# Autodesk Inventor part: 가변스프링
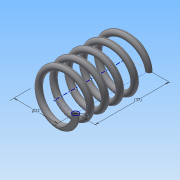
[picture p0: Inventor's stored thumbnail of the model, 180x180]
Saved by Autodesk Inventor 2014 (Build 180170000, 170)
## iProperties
Created: 2015-09
Part Number: 가변스프링
Material: Generic
Document SubType Name: Modeling
Designer: study
Density: 1 g/cm^3
Appearance: Default
Author: study
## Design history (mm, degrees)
sketch "스케치1"
  geometry: L1 (0, 0)-(11, 0); L2 (11, 0)-(11, 37); L3 (11, 37)-(0, 37); L4 (0, 37)-(0, 0); C1 r 1.5 at (11, 0)
  constraints: 8 end point, 2 parallel, 1 centre point, 1 coincident, 1 horizontal, 1 perpendicular
  dimensions: "d0" = 22 diameter of L2 L4; "d1" = 3 diameter of C1; "d2" = 37 distance between parallel lines of L1 L3 (derived)
feature "코일1" sketch "스케치1" pitch "d3" = 10; turns "d5" = 5; dims "d4" = 37 (= d2), "d6" = 0, angle "d7" = 90 deg, angle "d8" = 90 deg, "d9" = 0, "d10" = 0
node "작업 평면1"
sketch "스케치2"
  geometry: L1 (-12.5, 0)-(-9.5, 0) reference; 1 further point
  constraints: 1 horizontal alignment
extrude "돌출1" cut sketch "스케치2" distance "d12" = 10; taper "d13" = 0 deg
node "작업 평면2"
sketch "스케치3"
  geometry: L1 (-9.5, 0)-(-12.5, 0) reference; 1 further point
  constraints: 1 horizontal alignment
extrude "돌출2" cut sketch "스케치3" distance "d15" = 10; taper "d16" = 0 deg
node "솔리드1"
node "절단 모서리 투영1"
node "절단 모서리 투영2"
other parameters: "d11" = 0, "d14" = 37 (= d2)
